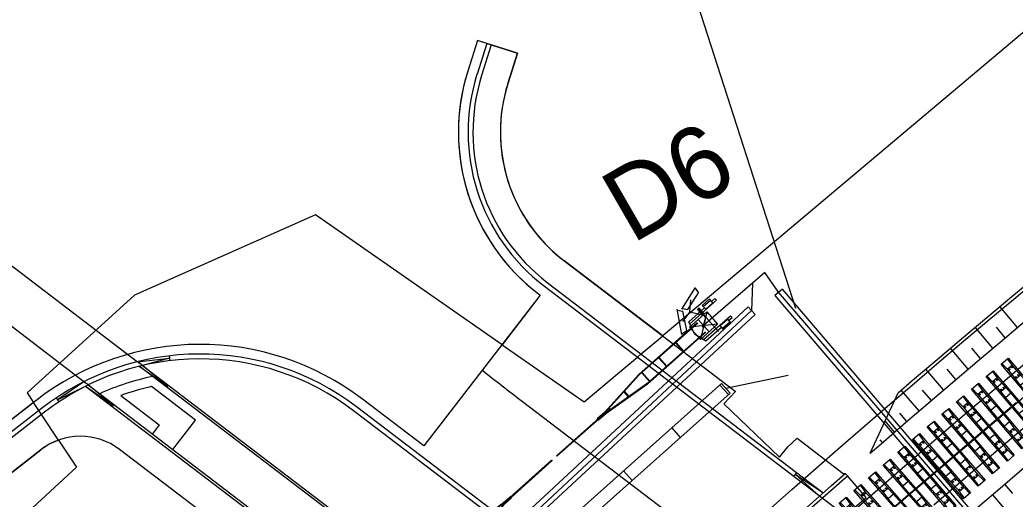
# Model space of a CAD drawing. Extents: x -759005 to -757278, y -1175311 to -1173953.
# Drawn here: x -758425.57 to -758394.73, y -1174837.27 to -1174822.42 of the extents above; entities that cross this region are included whole.
import ezdxf

# ---------------------------------------------------------------- set-up
doc = ezdxf.new("R2010")
doc.units = 0
for name, color, linetype in [('__NOR-dočasný zábor', 7, 'Continuous'), ('_NOR-návrh silná', 7, 'Continuous'), ('_NOR-návrh tenká', 7, 'Continuous'), ('_NOR-osa', 7, 'Continuous'), ('_NOR-popis', 7, 'Continuous'), ('_NOR-pražce', 7, 'Continuous'), ('_NOR-přejezdová konstrukce', 7, 'Continuous'), ('_NOR-sanace', 7, 'Continuous'), ('_NOR-svahy', 7, 'Continuous'), ('G_Obvod stavby', 7, 'Continuous'), ('KOS_kabely SSZT', 7, 'Continuous'), ('KOS_PZZ nové', 7, 'Continuous'), ('Vrstva 1', 7, 'Continuous')]:
    doc.layers.add(name, color=color, linetype=linetype)

# ---------------------------------------------------------------- blocks, each defined once
blk = doc.blocks.new('půdorys-SB8')
at = {"layer": '_NOR-pražce'}
for p, q in [((-1.21, 0.109), (-0.96, 0.095)), ((-0.96, 0.095), (-0.56, 0.099)), ((-0.96, 0.095), (-0.96, -0.095)), ((-0.56, 0.099), (-0.32, 0.109)), ((-0.56, 0.099), (-0.56, -0.1)), ((-0.32, 0.109), (0.32, 0.109)), ((-0.32, 0.109), (-0.32, -0.11)), ((0.56, 0.099), (0.32, 0.109)), ((0.32, -0.11), (0.32, 0.109)), ((0.96, 0.095), (0.56, 0.099)), ((0.56, 0.099), (0.56, -0.1)), ((1.21, 0.109), (0.96, 0.095)), ((0.96, 0.095), (0.96, -0.095)), ((-1.21, -0.11), (-0.96, -0.095)), ((-0.96, -0.095), (-0.56, -0.1)), ((-0.56, -0.1), (-0.32, -0.11)), ((-0.32, -0.11), (0.32, -0.11)), ((0.56, -0.1), (0.32, -0.11)), ((0.96, -0.095), (0.56, -0.1)), ((1.21, -0.11), (0.96, -0.095))]:
    blk.add_line(p, q, dxfattribs=at)
blk.add_lwpolyline([(-1.21, 0.142), (1.21, 0.142), (1.21, -0.142), (-1.21, -0.142)], close=True, dxfattribs=at)
for centre in [(-0.916, 0.048), (-0.604, 0.048), (0.604, 0.048), (0.916, 0.048), (-0.916, -0.048), (-0.604, -0.048), (0.604, -0.048), (0.916, -0.048)]:
    blk.add_circle(centre, 0.015, dxfattribs=at)
blk = doc.blocks.new('A$C45C32C5D')
for p, q in [((0.338, 0.725), (0, 0)), ((0.328, 0.702), (0.449, 0.568)), ((0.011, 0.023), (0.192, 0.016))]:
    blk.add_line(p, q)
blk.add_lwpolyline([(0.449, 0.568), (0.192, 0.016)])
blk = doc.blocks.new('A$C45E25FDC')
for p, q in [((0.029, 0.671), (0.224, 0.671)), ((0.341, 0.159), (0.341, 0.557)), ((0.341, 0.159), (0, 0))]:
    blk.add_line(p, q)
blk.add_arc((0.227, 0.557), 0.115, 0.0129, 91.4438)
blk = doc.blocks.new('Závora 8m')
for p, q in [((0.083, -0.373), (-0.058, -0.373)), ((-0.058, -0.448), (-0.058, -0.373)), ((1.054, -0.448), (-0.058, -0.448)), ((1.032, -0.373), (0.382, -0.373)), ((0.413, -1.026), (1.122, -0.517)), ((0.413, -0.517), (1.122, -1.026)), ((0.542, -0.323), (0.542, -1.27)), ((0.767, -0.517), (0.767, -1.026)), ((0.851, -0.571), (5.271, -0.571)), ((0.851, -0.591), (5.271, -0.591)), ((1.149, -0.771), (1.032, -0.373)), ((1.751, -0.591), (1.751, -0.951)), ((1.771, -0.591), (1.771, -0.951)), ((2.451, -0.591), (2.451, -0.951)), ((2.471, -0.591), (2.471, -0.951)), ((3.151, -0.591), (3.151, -0.951)), ((3.171, -0.591), (3.171, -0.951)), ((3.851, -0.591), (3.851, -0.951)), ((3.871, -0.591), (3.871, -0.951)), ((4.551, -0.591), (4.551, -0.951)), ((4.571, -0.591), (4.571, -0.951)), ((5.251, -0.591), (5.251, -0.951)), ((5.271, -0.571), (6.851, -0.741)), ((5.271, -0.591), (5.271, -0.951)), ((5.271, -0.591), (6.851, -0.761)), ((1.149, -0.771), (1.032, -1.17)), ((6.851, -0.781), (5.271, -0.951)), ((5.271, -0.971), (6.851, -0.801)), ((5.951, -0.665), (5.951, -0.878)), ((5.971, -0.667), (5.971, -0.876)), ((6.651, -0.74), (6.651, -0.803)), ((6.671, -0.742), (6.671, -0.801)), ((6.851, -0.741), (7.151, -0.741)), ((8.851, -0.761), (6.851, -0.761)), ((6.851, -0.761), (6.851, -0.781)), ((6.851, -0.761), (7.151, -0.761)), ((8.851, -0.781), (6.851, -0.781)), ((6.851, -0.781), (7.151, -0.781)), ((6.851, -0.801), (7.151, -0.801)), ((7.151, -0.741), (7.151, -0.761)), ((7.151, -0.801), (7.151, -0.781)), ((8.851, -0.761), (8.851, -0.781)), ((1.054, -1.095), (-0.058, -1.095)), ((-0.058, -1.095), (-0.058, -1.17)), ((0.083, -1.17), (-0.058, -1.17)), ((1.032, -1.17), (0.382, -1.17)), ((0.851, -0.951), (5.271, -0.951)), ((0.851, -0.971), (5.271, -0.971))]:
    blk.add_line(p, q)
for points in [[(0.382, -0.434), (0.083, -0.434), (0.083, -0.274), (0.382, -0.274)], [(0.382, -0.324), (0.083, -0.324), (0.083, -0.274), (0.382, -0.274)], [(0.413, -0.517), (1.122, -0.517), (1.122, -1.026), (0.413, -1.026)], [(0.382, -1.109), (0.083, -1.109), (0.083, -1.269), (0.382, -1.269)], [(0.382, -1.219), (0.083, -1.219), (0.083, -1.269), (0.382, -1.269)]]:
    blk.add_lwpolyline(points, close=True)
blk.add_lwpolyline([(0.507, -1.048), (0.507, -1.27), (0.578, -1.27), (0.578, -1.048)])
for start, end in [(130.1075, 310.1075), (310.1075, 130.1075)]:
    blk.add_arc((0.767, -0.771), 0.0422, start, end)
blk = doc.blocks.new('Závora 6m')
for p, q in [((0.083, -0.373), (-0.058, -0.373)), ((-0.058, -0.448), (-0.058, -0.373)), ((1.054, -0.448), (-0.058, -0.448)), ((1.032, -0.373), (0.382, -0.373)), ((0.413, -1.026), (1.122, -0.517)), ((0.413, -0.517), (1.122, -1.026)), ((0.542, -0.323), (0.542, -1.27)), ((0.767, -0.517), (0.767, -1.026)), ((0.851, -0.571), (3.271, -0.571)), ((0.851, -0.591), (3.271, -0.591)), ((1.149, -0.771), (1.032, -0.373)), ((1.751, -0.591), (1.751, -0.951)), ((1.771, -0.591), (1.771, -0.951)), ((2.451, -0.591), (2.451, -0.951)), ((2.471, -0.591), (2.471, -0.951)), ((3.151, -0.591), (3.151, -0.951)), ((3.171, -0.591), (3.171, -0.951)), ((3.271, -0.571), (4.851, -0.741)), ((3.271, -0.591), (4.851, -0.761)), ((1.149, -0.771), (1.032, -1.17)), ((4.851, -0.781), (3.271, -0.951)), ((3.271, -0.971), (4.851, -0.801)), ((3.951, -0.665), (3.951, -0.878)), ((3.971, -0.667), (3.971, -0.876)), ((4.651, -0.74), (4.651, -0.803)), ((4.671, -0.742), (4.671, -0.801)), ((4.851, -0.741), (5.151, -0.741)), ((6.851, -0.761), (4.851, -0.761)), ((4.851, -0.761), (4.851, -0.781)), ((4.851, -0.761), (5.151, -0.761)), ((6.851, -0.781), (4.851, -0.781)), ((4.851, -0.781), (5.151, -0.781)), ((4.851, -0.801), (5.151, -0.801)), ((5.151, -0.741), (5.151, -0.761)), ((5.151, -0.801), (5.151, -0.781)), ((6.851, -0.761), (6.851, -0.781)), ((1.054, -1.095), (-0.058, -1.095)), ((-0.058, -1.095), (-0.058, -1.17)), ((0.083, -1.17), (-0.058, -1.17)), ((1.032, -1.17), (0.382, -1.17)), ((0.851, -0.951), (3.271, -0.951)), ((0.851, -0.971), (3.271, -0.971))]:
    blk.add_line(p, q)
for points in [[(0.382, -0.434), (0.083, -0.434), (0.083, -0.274), (0.382, -0.274)], [(0.382, -0.324), (0.083, -0.324), (0.083, -0.274), (0.382, -0.274)], [(0.413, -0.517), (1.122, -0.517), (1.122, -1.026), (0.413, -1.026)], [(0.382, -1.109), (0.083, -1.109), (0.083, -1.269), (0.382, -1.269)], [(0.382, -1.219), (0.083, -1.219), (0.083, -1.269), (0.382, -1.269)]]:
    blk.add_lwpolyline(points, close=True)
blk.add_lwpolyline([(0.507, -1.048), (0.507, -1.27), (0.578, -1.27), (0.578, -1.048)])
for start, end in [(130.1075, 310.1075), (310.1075, 130.1075)]:
    blk.add_arc((0.767, -0.771), 0.0422, start, end)

msp = doc.modelspace()

# ---------------------------------------------------------------- linework, layer by layer
at = {"layer": '__NOR-dočasný zábor'}
for p, q in [((-758411.39, -1174823.058), (-758411.69, -1174824.012)), ((-758411.104, -1174823.148), (-758411.39, -1174823.058)), ((-758410.96, -1174823.193), (-758411.104, -1174823.148)), ((-758410.15, -1174823.448), (-758410.96, -1174823.193)), ((-758410.449, -1174824.402), (-758410.15, -1174823.448)), ((-758405.651, -1174832.209), (-758408.71, -1174829.878)), ((-758409.498, -1174830.912), (-758409.442, -1174830.955)), ((-758409.442, -1174830.955), (-758410.628, -1174832.486)), ((-758410.628, -1174832.486), (-758408.08, -1174834.26)), ((-758406.317, -1174832.771), (-758405.651, -1174832.209)), ((-758406.434, -1174832.87), (-758406.317, -1174832.771)), ((-758406.79, -1174833.17), (-758406.434, -1174832.87)), ((-758408.08, -1174834.26), (-758406.79, -1174833.17)), ((-758425.144, -1174834.274), (-758428.234, -1174836.675)), ((-758424.978, -1174834.525), (-758425.144, -1174834.274)), ((-758424.894, -1174834.65), (-758424.978, -1174834.525)), ((-758424.368, -1174835.441), (-758424.894, -1174834.65))]:
    msp.add_line(p, q, dxfattribs=at)
msp.add_lwpolyline([(-758427.958, -1174837.03), (-758427.436, -1174837.702), (-758424.916, -1174835.743)], dxfattribs=at)
for centre, radius, start, end in [((-758405.68, -1174825.901), 6.3, 162.5481, 188.8894), ((-758405.68, -1174825.901), 5, 162.5481, 212.3104), ((-758405.68, -1174825.901), 6.3, 188.8894, 232.6885), ((-758405.68, -1174825.901), 5, 212.3104, 232.6885), ((-758423.689, -1174837.322), 2, 109.854, 127.8448)]:
    msp.add_arc(centre, radius, start, end, dxfattribs=at)
at = {"layer": '_NOR-návrh silná'}
for p, q in [((-758421.766, -1174833.13), (-758401.3, -1174848.727)), ((-758423.45, -1174833.732), (-758401.745, -1174850.274))]:
    msp.add_line(p, q, dxfattribs=at)
for points in [[(-758411.104, -1174823.148), (-758411.403, -1174824.102)], [(-758409.317, -1174830.673), (-758395.764, -1174841.002)], [(-758424.891, -1174834.458), (-758428.05, -1174836.912)], [(-758399.411, -1174846.395), (-758415.134, -1174834.412)]]:
    msp.add_lwpolyline(points, dxfattribs=at)
for centre, radius, start, end in [((-758405.68, -1174825.901), 6, 162.5481, 232.6885), ((-758419.983, -1174840.775), 8, 52.6885, 127.8448)]:
    msp.add_arc(centre, radius, start, end, dxfattribs=at)
at = {"layer": '_NOR-návrh tenká'}
for p, q in [((-758427.927, -1174828.434), (-758421.919, -1174833.013)), ((-758423.583, -1174833.631), (-758428.307, -1174830.031)), ((-758421.919, -1174833.013), (-758420.928, -1174832.907)), ((-758421.766, -1174833.13), (-758421.919, -1174833.013)), ((-758420.928, -1174832.907), (-758421.766, -1174833.13)), ((-758420.937, -1174832.832), (-758420.919, -1174832.981)), ((-758421.866, -1174833.154), (-758420.994, -1174833.768)), ((-758420.994, -1174833.768), (-758421.766, -1174833.13)), ((-758423.583, -1174833.631), (-758424.404, -1174834.198)), ((-758423.45, -1174833.732), (-758423.583, -1174833.631)), ((-758410.412, -1174839.554), (-758403.826, -1174833.687)), ((-758403.826, -1174833.687), (-758403.56, -1174833.986)), ((-758403.693, -1174833.836), (-758401.766, -1174833.434)), ((-758424.404, -1174834.198), (-758423.53, -1174833.772)), ((-758423.53, -1174833.772), (-758422.679, -1174834.37)), ((-758422.679, -1174834.37), (-758423.45, -1174833.732)), ((-758420.97, -1174833.736), (-758421.019, -1174833.8)), ((-758410.146, -1174839.852), (-758403.56, -1174833.986)), ((-758403.878, -1174833.734), (-758403.612, -1174834.032)), ((-758424.445, -1174834.135), (-758424.362, -1174834.26)), ((-758422.655, -1174834.338), (-758422.703, -1174834.402)), ((-758405.372, -1174835.064), (-758405.106, -1174835.363)), ((-758406.865, -1174836.394), (-758406.599, -1174836.693)), ((-758401.584, -1174836.566), (-758401.493, -1174836.447)), ((-758400.789, -1174837.173), (-758401.539, -1174836.507)), ((-758401.539, -1174836.507), (-758400.673, -1174837.072))]:
    msp.add_line(p, q, dxfattribs=at)
for points in [[(-758411.104, -1174823.148), (-758411.39, -1174823.058), (-758411.69, -1174824.012)], [(-758411.104, -1174823.148), (-758410.96, -1174823.193), (-758411.26, -1174824.147)], [(-758410.96, -1174823.193), (-758410.15, -1174823.448), (-758410.449, -1174824.402)], [(-758399.22, -1174835.845), (-758398.357, -1174833.975), (-758397.917, -1174833.598), (-758397.15, -1174832.943), (-758396.382, -1174832.291), (-758395.611, -1174831.641), (-758394.838, -1174830.994), (-758394.062, -1174830.349), (-758393.285, -1174829.706), (-758392.507, -1174829.068)], [(-758408.71, -1174829.878), (-758403.402, -1174833.923), (-758403.405, -1174833.947), (-758403.761, -1174834.321), (-758402.034, -1174835.972), (-758401.778, -1174835.646), (-758401.489, -1174835.381), (-758400.057, -1174836.473), (-758399.995, -1174836.478)], [(-758399.22, -1174835.845), (-758398.887, -1174835.555), (-758398.127, -1174834.898), (-758397.364, -1174834.243), (-758396.599, -1174833.591), (-758395.833, -1174832.94), (-758395.064, -1174832.292), (-758394.293, -1174831.646), (-758393.52, -1174831.003), (-758392.745, -1174830.362), (-758391.968, -1174829.725)], [(-758409.226, -1174830.554), (-758400.674, -1174837.072)], [(-758409.498, -1174830.912), (-758409.442, -1174830.955), (-758413.055, -1174835.619), (-758414.952, -1174834.174)], [(-758396.95, -1174838.443), (-758396.628, -1174838.163), (-758395.875, -1174837.512), (-758395.12, -1174836.864), (-758394.364, -1174836.218), (-758393.605, -1174835.574), (-758392.844, -1174834.933), (-758392.082, -1174834.295), (-758391.318, -1174833.659), (-758390.551, -1174833.025), (-758389.782, -1174832.394)], [(-758399.743, -1174837.628), (-758398.989, -1174836.968), (-758398.232, -1174836.311), (-758397.474, -1174835.656), (-758396.714, -1174835.003), (-758395.951, -1174834.352), (-758395.187, -1174833.704), (-758394.421, -1174833.058)], [(-758408.073, -1174843.666), (-758421.866, -1174833.154)], [(-758423.53, -1174833.772), (-758409.191, -1174844.7)], [(-758420.824, -1174835.734), (-758420.127, -1174834.819), (-758421.484, -1174833.785)], [(-758425.075, -1174834.221), (-758428.234, -1174836.675), (-758428.05, -1174836.912)], [(-758422.441, -1174834.061), (-758421.248, -1174834.97), (-758421.46, -1174835.249)], [(-758409.998, -1174834.24), (-758401.824, -1174840.47)], [(-758424.799, -1174834.576), (-758427.958, -1174837.03), (-758428.05, -1174836.912)], [(-758405.836, -1174841.687), (-758415.225, -1174834.532)], [(-758397.25, -1174837.445), (-758396.495, -1174836.792), (-758395.738, -1174836.142), (-758394.979, -1174835.494), (-758394.218, -1174834.849)], [(-758424.916, -1174835.743), (-758427.436, -1174837.702), (-758427.958, -1174837.03)], [(-758413.475, -1174842.592), (-758422.476, -1174835.732)]]:
    msp.add_lwpolyline(points, dxfattribs=at)
for centre, radius, start, end in [((-758405.68, -1174825.901), 6.3, 162.5481, 232.6885), ((-758405.68, -1174825.901), 5.85, 162.5481, 232.6885), ((-758405.68, -1174825.901), 5, 162.5481, 232.6885), ((-758419.983, -1174840.775), 8.3, 52.6885, 127.8448), ((-758419.983, -1174840.775), 7.85, 52.6885, 127.8448), ((-758349.383, -1174754.705), 100, 231.78754, 232.68848), ((-758419.983, -1174840.775), 7.45, 101.3579, 114.6673), ((-758419.983, -1174840.775), 7.15, 102.1205, 110.1095), ((-758423.689, -1174837.322), 2, 52.6885, 127.8448)]:
    msp.add_arc(centre, radius, start, end, dxfattribs=at)
at = {"layer": '_NOR-osa'}
msp.add_lwpolyline([(-758398.496, -1174837.534), (-758397.741, -1174836.878), (-758396.984, -1174836.224), (-758396.226, -1174835.573), (-758395.465, -1174834.923), (-758394.703, -1174834.276)], dxfattribs=at)
at = {"layer": '_NOR-popis'}
msp.add_lwpolyline([(-758411.267, -1174770.178), (-758420.309, -1174773.091), (-758401.541, -1174831.358)], dxfattribs=at)
at = {"layer": '_NOR-přejezdová konstrukce'}
msp.add_line((-758399.349, -1174837.217), (-758399.93, -1174836.553), dxfattribs=at)
for points in [[(-758406.208, -1174842.161), (-758406.276, -1174842.087), (-758405.669, -1174841.535), (-758404.925, -1174840.86), (-758404.179, -1174840.188), (-758403.432, -1174839.517), (-758402.682, -1174838.848), (-758401.931, -1174838.18), (-758401.178, -1174837.515), (-758400.423, -1174836.852), (-758399.995, -1174836.478), (-758399.93, -1174836.553)], [(-758406.208, -1174842.161), (-758405.602, -1174841.609), (-758404.858, -1174840.934), (-758404.112, -1174840.262), (-758403.365, -1174839.591), (-758402.616, -1174838.922), (-758401.865, -1174838.255), (-758401.112, -1174837.59), (-758400.358, -1174836.927), (-758399.93, -1174836.553)], [(-758405.615, -1174842.813), (-758405.009, -1174842.262), (-758404.266, -1174841.589), (-758403.522, -1174840.918), (-758402.777, -1174840.248), (-758402.029, -1174839.581), (-758401.28, -1174838.915), (-758400.529, -1174838.252), (-758399.776, -1174837.59), (-758399.349, -1174837.217)]]:
    msp.add_lwpolyline(points, dxfattribs=at)
at = {"layer": '_NOR-sanace'}
msp.add_lwpolyline([(-758402.407, -1174837.643), (-758401.653, -1174836.976), (-758400.897, -1174836.312), (-758400.138, -1174835.649), (-758399.378, -1174834.988), (-758398.616, -1174834.33), (-758397.852, -1174833.673), (-758397.085, -1174833.019), (-758396.317, -1174832.367), (-758395.546, -1174831.718), (-758394.774, -1174831.071), (-758393.999, -1174830.426)], dxfattribs=at)
at = {"layer": '_NOR-svahy'}
for points in [[(-758394.656, -1174831.95), (-758395.202, -1174831.299)], [(-758395.422, -1174832.594), (-758395.97, -1174831.944)], [(-758395.039, -1174832.272), (-758395.312, -1174831.946)], [(-758396.185, -1174833.239), (-758396.735, -1174832.591)], [(-758395.804, -1174832.916), (-758396.078, -1174832.591)], [(-758396.947, -1174833.887), (-758397.499, -1174833.241)], [(-758396.567, -1174833.563), (-758396.842, -1174833.239)], [(-758397.707, -1174834.538), (-758398.261, -1174833.893)], [(-758397.327, -1174834.212), (-758397.603, -1174833.889)], [(-758398.086, -1174834.863), (-758398.307, -1174834.606)], [(-758398.465, -1174835.19), (-758398.76, -1174834.848)], [(-758398.843, -1174835.517), (-758398.917, -1174835.432)], [(-758399.22, -1174835.845), (-758399.22, -1174835.845)], [(-758395.057, -1174836.81), (-758394.813, -1174837.095)], [(-758395.436, -1174837.135), (-758394.948, -1174837.704)]]:
    msp.add_lwpolyline(points, dxfattribs=at)
at = {"layer": 'G_Obvod stavby'}
for p, q in [((-758411.39, -1174823.058), (-758411.69, -1174824.012)), ((-758411.104, -1174823.148), (-758411.39, -1174823.058)), ((-758410.96, -1174823.193), (-758411.104, -1174823.148)), ((-758410.15, -1174823.448), (-758410.96, -1174823.193)), ((-758410.449, -1174824.402), (-758410.15, -1174823.448)), ((-758405.651, -1174832.209), (-758408.71, -1174829.878)), ((-758409.498, -1174830.912), (-758409.442, -1174830.955)), ((-758409.442, -1174830.955), (-758410.628, -1174832.486)), ((-758405.64, -1174832.2), (-758405.651, -1174832.209)), ((-758425.144, -1174834.274), (-758428.234, -1174836.675))]:
    msp.add_line(p, q, dxfattribs=at)
for points in [[(-758392.72, -1174840.756), (-758391.23, -1174838.56), (-758368.37, -1174821.64), (-758340.31, -1174807.33), (-758320.27, -1174796.89), (-758301, -1174790.21), (-758267.96, -1174782.93), (-758224.96, -1174775.27), (-758184.87, -1174772.83), (-758142.71, -1174770.26), (-758089.84, -1174768.68), (-758106.02, -1174731.44), (-758149.09, -1174725.67), (-758199.62, -1174726.6), (-758225.76, -1174732.36), (-758252.17, -1174738.18), (-758254.97, -1174739.34), (-758266.58, -1174744.16), (-758279.45, -1174749.49), (-758302.42, -1174759.02), (-758331.68, -1174770.24), (-758367.17, -1174799.81), (-758405.64, -1174832.2)], [(-758410.628, -1174832.486), (-758416.41, -1174828.46), (-758422.01, -1174830.95), (-758425.34, -1174833.98), (-758425.144, -1174834.274)], [(-758424.368, -1174835.441), (-758423.81, -1174836.28), (-758457.56, -1174867.46)], [(-758427.958, -1174837.03), (-758427.436, -1174837.702), (-758424.916, -1174835.743)]]:
    msp.add_lwpolyline(points, dxfattribs=at)
for centre, radius, start, end in [((-758405.68, -1174825.901), 6.3, 162.5481, 188.8894), ((-758405.68, -1174825.901), 5, 162.5481, 212.3104), ((-758405.68, -1174825.901), 6.3, 188.8894, 232.6885), ((-758405.68, -1174825.901), 5, 212.3104, 232.6885), ((-758423.689, -1174837.322), 2, 109.854, 127.8448)]:
    msp.add_arc(centre, radius, start, end, dxfattribs=at)
at = {"layer": 'KOS_kabely SSZT'}
for points in [[(-758393.377, -1174840.127), (-758394.523, -1174839.636), (-758402.059, -1174830.861), (-758402.489, -1174830.243), (-758402.873, -1174830.574), (-758402.896, -1174831.429), (-758411.837, -1174839.758), (-758412.685, -1174838.202), (-758411.837, -1174839.758), (-758414.56, -1174842.041), (-758415.093, -1174841.478), (-758414.56, -1174842.041), (-758421.625, -1174846.632), (-758424.748, -1174843.672)], [(-758402.873, -1174830.574), (-758404.383, -1174831.895)], [(-758401.943, -1174830.766), (-758402.175, -1174830.957), (-758395.093, -1174839.249), (-758394.861, -1174839.058), (-758401.943, -1174830.766)]]:
    msp.add_lwpolyline(points, dxfattribs=at)
msp.add_lwpolyline([(-758411.517, -1174839.221), (-758403.003, -1174831.313), (-758402.788, -1174831.545), (-758411.302, -1174839.452)], close=True, dxfattribs=at)
at = {"layer": 'KOS_PZZ nové'}
msp.add_line((-758404.807, -1174831.471), (-758404.774, -1174831.096), dxfattribs=at)
at = {"layer": 'Vrstva 1'}
for points in [[(-758443.817, -1174881.252), (-758441.673, -1174879.1), (-758423.412, -1174860.854), (-758412.446, -1174850.23), (-758405.322, -1174843.614), (-758399.028, -1174837.996), (-758392.64, -1174832.554), (-758380.106, -1174822.693), (-758371.773, -1174816.721), (-758363.37, -1174811.125), (-758354.46, -1174805.649), (-758345.526, -1174800.592), (-758336.614, -1174795.909), (-758327.338, -1174791.462), (-758317.813, -1174787.314), (-758307.666, -1174783.315), (-758298.059, -1174779.921), (-758285.017, -1174775.914), (-758275.047, -1174773.289)], [(-758443.817, -1174881.252), (-758441.673, -1174879.1), (-758423.412, -1174860.854), (-758412.446, -1174850.23), (-758405.322, -1174843.614), (-758399.028, -1174837.996), (-758392.64, -1174832.554), (-758380.106, -1174822.693), (-758371.773, -1174816.721), (-758363.37, -1174811.125), (-758354.46, -1174805.649), (-758350.18, -1174803.227)]]:
    msp.add_lwpolyline(points, dxfattribs=at)

# ---------------------------------------------------------------- block references
at = {"layer": '_NOR-pražce'}
for p, rotation in [((-758394.28, -1174833.92), -49.869858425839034), ((-758394.737, -1174834.306), -49.69116733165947), ((-758395.195, -1174834.694), -49.691167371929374), ((-758395.65, -1174835.081), -49.51584778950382), ((-758396.106, -1174835.47), -49.51584780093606), ((-758396.56, -1174835.86), -49.34389977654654), ((-758397.013, -1174836.249), -49.17532329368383), ((-758397.468, -1174836.641), -49.17532330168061), ((-758397.919, -1174837.033), -49.01011836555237), ((-758398.372, -1174837.426), -49.01011829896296), ((-758398.823, -1174837.819), -48.848284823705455), ((-758399.273, -1174838.213), -48.68982295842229)]:
    msp.add_blockref('půdorys-SB8', p, dxfattribs=dict(at, rotation=rotation))
at = {"layer": 'KOS_PZZ nové'}
for name, p, yscale, rotation in [('A$C45C32C5D', (-758404.63, -1174830.708), -1, -57.520567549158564), ('A$C45C32C5D', (-758405.206, -1174831.385), -1.0000000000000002, -13.953639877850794), ('A$C45E25FDC', (-758405.042, -1174831.765), -1, 76.38095475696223)]:
    msp.add_blockref(name, p, dxfattribs=dict(at, yscale=yscale, rotation=rotation))
for name, p, rotation in [('Závora 6m', (-758403.297, -1174831.963), -138.41254315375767), ('Závora 8m', (-758416.18, -1174841.418), 42.00076019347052)]:
    msp.add_blockref(name, p, dxfattribs=dict(at, rotation=rotation))

# ---------------------------------------------------------------- texts
at = {"layer": '__NOR-dočasný zábor'}
msp.add_text('D6', height=2.2727, rotation=30, dxfattribs=at).set_placement((-758406.605, -1174829.378))

doc.saveas('drawing.dxf')
